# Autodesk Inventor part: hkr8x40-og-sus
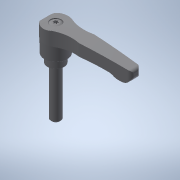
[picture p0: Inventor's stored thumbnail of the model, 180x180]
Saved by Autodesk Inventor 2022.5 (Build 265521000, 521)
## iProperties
Created: 2017-09
Part Number: hkr8x40-og-sus
Material: 一般
Document SubType Name: Modeling
Designer: imaocorp
Density: 1 g/cm^3
Appearance: 既定
Author: imaocorp
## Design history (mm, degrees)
node "hkr8x40-og-sus.x_t1"
node "hkr8x40-og-sus"
node "Base1"
